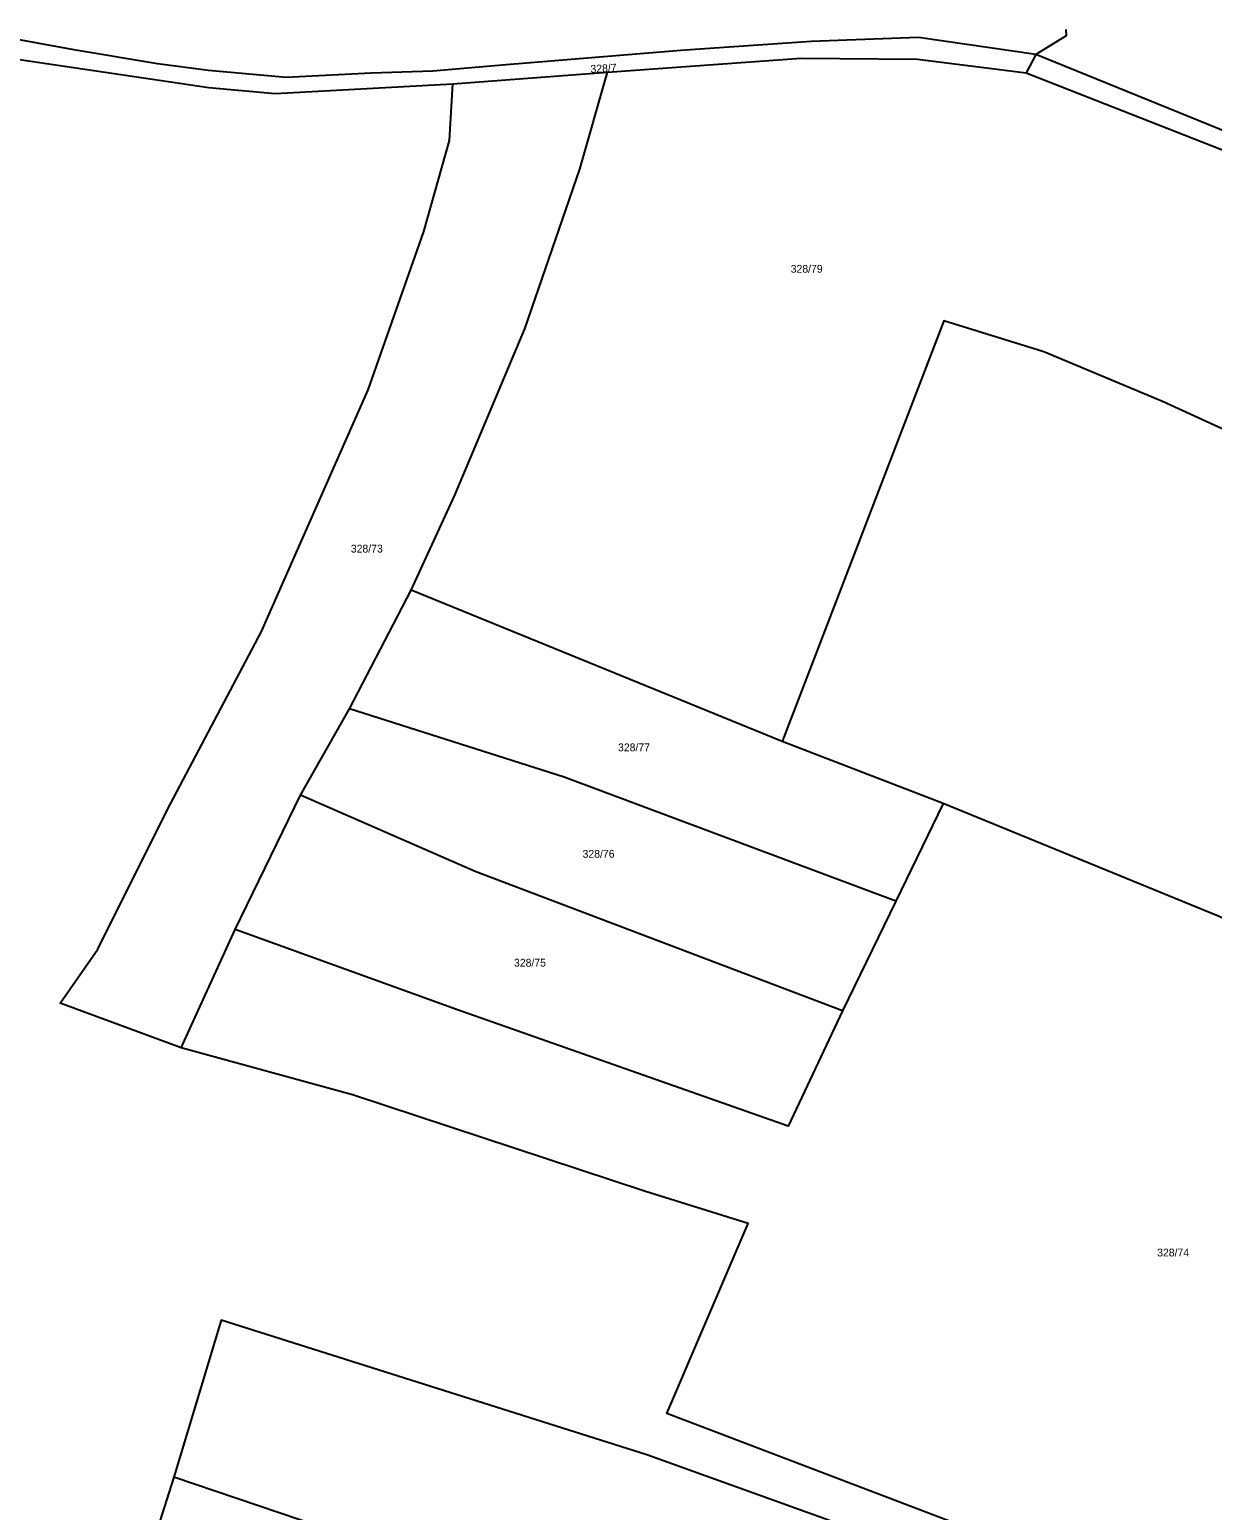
# Model space of a CAD drawing. Extents: x -783948 to -781889, y -1005870 to -1004430.
# Drawn here: x -782402.5 to -782144.9, y -1004993.6 to -1004671.2 of the extents above; entities that cross this region are included whole.
import ezdxf

# ---------------------------------------------------------------- set-up
doc = ezdxf.new("R2010")
doc.units = 0
doc.layers.add('Vrstva 1', color=7, linetype='Continuous')
doc.layers.add('Vrstva 2', color=7, linetype='Continuous')

msp = doc.modelspace()

# ---------------------------------------------------------------- linework, layer by layer
at = {"layer": 'Vrstva 1'}
for p, q in [((-782176.82, -1004671.23), (-782176.77, -1004672.62)), ((-782392.38, -1004675.73), (-782409.14, -1004672.64)), ((-782260.69, -1004675.75), (-782298.73, -1004678.9)), ((-782176.77, -1004672.62), (-782183.39, -1004676.65)), ((-782183.39, -1004676.65), (-782185.46, -1004680.64)), ((-782310.28, -1004683.02), (-782276.61, -1004680.5)), ((-782185.46, -1004680.64), (-782082.31, -1004721.17)), ((-782332.84, -1004819.08), (-782319.41, -1004793.29)), ((-782238.61, -1004826.25), (-782319.41, -1004793.29)), ((-782343.46, -1004837.9), (-782332.84, -1004819.08)), ((-782203.57, -1004839.7), (-782238.61, -1004826.25)), ((-782357.68, -1004867.12), (-782343.46, -1004837.9)), ((-782203.57, -1004839.7), (-782213.85, -1004860.99)), ((-782213.85, -1004860.99), (-782225.45, -1004884.87)), ((-782369.47, -1004892.92), (-782357.68, -1004867.12)), ((-782371.08, -1004986.39), (-782380.26, -1005015.34))]:
    msp.add_line(p, q, dxfattribs=at)
for points in [[(-782422.67, -1004674.79), (-782409.15, -1004677.07), (-782363.43, -1004683.82), (-782349.02, -1004685.11), (-782310.28, -1004683.02)], [(-782328.11, -1004680.69), (-782346.61, -1004681.66), (-782363.53, -1004680.15), (-782374.6, -1004678.69), (-782392.38, -1004675.73)], [(-782183.39, -1004676.65), (-782208.93, -1004672.97), (-782232.28, -1004673.8), (-782260.69, -1004675.75)], [(-782298.73, -1004678.9), (-782314.68, -1004680.28), (-782328.11, -1004680.69)], [(-782276.61, -1004680.5), (-782234.46, -1004677.44), (-782209.14, -1004677.63), (-782185.46, -1004680.64)], [(-782044.78, -1004733.61), (-782081.63, -1004718.02), (-782183.39, -1004676.65)], [(-782319.41, -1004793.29), (-782309.85, -1004772.6), (-782294.65, -1004736.4), (-782282.63, -1004701.6), (-782276.61, -1004680.5)], [(-782369.47, -1004892.92), (-782395.8, -1004883.2), (-782387.64, -1004871.41), (-782372.43, -1004841.03), (-782351.95, -1004802.25), (-782328.76, -1004749.65), (-782316.61, -1004715.2), (-782311.02, -1004695.39), (-782310.28, -1004683.02)], [(-782082.31, -1004721.17), (-782105.71, -1004775.15), (-782155.81, -1004752.17), (-782181.61, -1004741.36), (-782203.38, -1004734.64), (-782238.61, -1004826.25)], [(-782213.85, -1004860.99), (-782286.04, -1004834.01), (-782332.84, -1004819.08)], [(-782225.45, -1004884.87), (-782305.45, -1004854.49), (-782343.46, -1004837.9)], [(-782003.24, -1004934.69), (-782017.49, -1004925.27), (-782094.87, -1004885.47), (-782109.93, -1004879.2), (-782143.79, -1004864.19), (-782203.57, -1004839.7)], [(-782225.45, -1004884.87), (-782237.32, -1004910), (-782309.52, -1004884.54), (-782357.68, -1004867.12)], [(-782164.3, -1005013.28), (-782179.86, -1005004.46), (-782263.73, -1004972.51), (-782246.02, -1004931.17), (-782268.59, -1004924.1), (-782332.13, -1004903.18), (-782369.47, -1004892.92)], [(-782167.64, -1005020.28), (-782228.54, -1004995.74), (-782268.06, -1004981.53), (-782360.79, -1004952.21), (-782371.08, -1004986.39)], [(-782186.06, -1005051.26), (-782302.45, -1005009.61), (-782371.08, -1004986.39)]]:
    msp.add_lwpolyline(points, dxfattribs=at)

# ---------------------------------------------------------------- texts
at = {"layer": 'Vrstva 2'}
msp.add_text('328/7', height=1.7, rotation=3, dxfattribs=at).set_placement((-782280.3, -1004680.65))
for s, p in [('328/79', (-782236.74, -1004724.16)), ('328/73', (-782332.52, -1004785.08)), ('328/77', (-782274.34, -1004828.35)), ('328/76', (-782282.06, -1004851.53)), ('328/75', (-782296.99, -1004875.23)), ('328/74', (-782156.94, -1004938.33))]:
    msp.add_text(s, height=1.7, dxfattribs=at).set_placement(p)

doc.saveas('drawing.dxf')
